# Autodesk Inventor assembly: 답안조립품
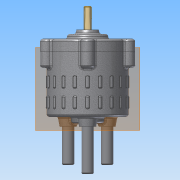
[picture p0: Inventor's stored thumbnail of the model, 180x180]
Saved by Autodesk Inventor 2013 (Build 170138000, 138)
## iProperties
Created: 2016-01
Part Number: 답안조립품
Document SubType Name: Assembly
Designer: Administrator
Mass: 2168.51 g
Surface Area: 1791.53 cm^2
Volume: 441.319 cm^3
Density: 4.91369 g/cm^3
Author: Administrator
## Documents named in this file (14)
- C:\Users\Administrator\Desktop\360106V1028\답안조립품.iam
- C:\Users\Administrator\Desktop\360106V1028\본체.ipt
- C:\Users\Administrator\Desktop\360106V1028\커버.ipt
- C:\Users\Administrator\Desktop\360106V1028\베어링 NA 4900.ipt
- C:\Users\Administrator\Desktop\360106V1028\오일실.ipt
- C:\Users\Administrator\Desktop\360106V1028\메인 축.ipt
- C:\Users\Administrator\Desktop\360106V1028\멈춤링 22 x 1.2.ipt
- C:\Users\Administrator\Desktop\360106V1028\판캠.ipt
- C:\Users\Administrator\Desktop\360106V1028\멈춤링 10 x 1.ipt
- C:\Users\Administrator\Desktop\360106V1028\M5x0.8x20.ipt
- C:\Users\Administrator\Desktop\360106V1028\슬라이드 축.ipt
- C:\Users\Administrator\Desktop\360106V1028\가변 스프링 - 1.ipt
- C:\Users\Administrator\Desktop\360106V1028\가변 스프링 - 2.ipt
- C:\Users\Administrator\Desktop\360106V1028\가변 스프링 - 3.ipt
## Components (8 placed, 4 different names)
1. M5x0.8x20:1
2. M5x0.8x20:2
3. M5x0.8x20:3
4. M5x0.8x20:4
5. M5x0.8x20:5
6. 가변 스프링 - 1:1
7. 가변 스프링 - 2:1
8. 가변 스프링 - 3:1
